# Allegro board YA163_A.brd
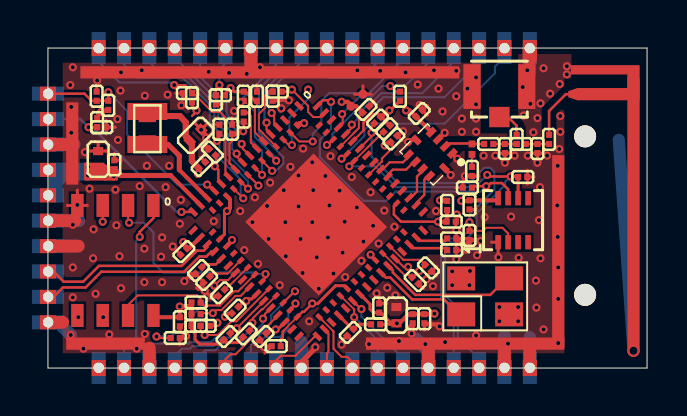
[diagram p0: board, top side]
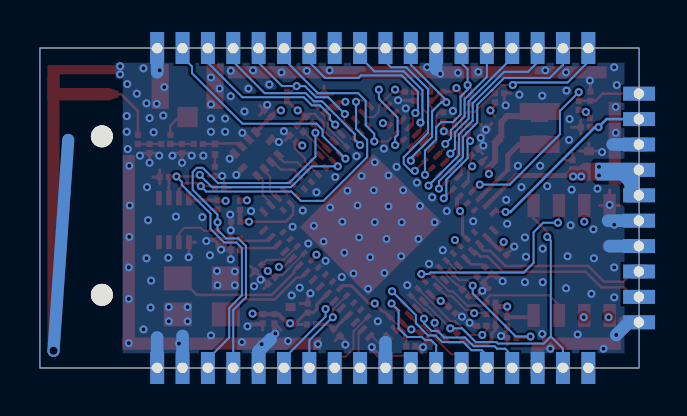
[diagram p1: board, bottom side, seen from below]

Outline 30 x 16 mm; copper layers: TOP, GND, PWR, BOTTOM. Coordinates in mm from the lower left corner of the outline.
Outline path: 0,16 0,13.96 arc(0.25,13.71) 0,13.47 0,12.69 arc(0.25,12.44) 0,12.2 0,11.42 arc(0.25,11.17) 0,10.93 0,10.15 arc(0.25,9.9) 0,9.66 0,8.88 arc(0.25,8.63) 0,8.39 0,7.61 arc(0.25,7.36) 0,7.12 0,6.34 arc(0.25,6.09) 0,5.85 0,5.07 arc(0.25,4.82) 0,4.58 0,3.8 arc(0.25,3.55) 0,3.31 0,2.53 arc(0.25,2.28) 0,2.04 0,0 2.29,0 arc(2.54,0.25) 2.79,0 3.56,0 arc(3.81,0.25) 4.06,0 4.83,0 arc(5.08,0.25) 5.33,0 6.1,0 arc(6.35,0.25) 6.6,0 7.37,0 arc(7.62,0.25) 7.87,0 8.64,0 arc(8.89,0.25) 9.14,0 9.91,0 arc(10.16,0.25) 10.41,0 11.18,0 arc(11.43,0.25) 11.68,0 12.45,0 arc(12.7,0.25) 12.95,0 13.72,0 arc(13.97,0.25) 14.22,0 14.99,0 arc(15.24,0.25) 15.49,0 16.26,0 arc(16.51,0.25) 16.76,0 17.53,0 arc(17.78,0.25) 18.03,0 18.8,0 arc(19.05,0.25) 19.3,0 20.07,0 arc(20.32,0.25) 20.57,0 21.34,0 arc(21.59,0.25) 21.84,0 22.61,0 arc(22.86,0.25) 23.11,0 23.88,0 arc(24.13,0.25) 24.38,0 30,0 30,16 24.38,16 arc(24.13,15.75) 23.88,16 23.11,16 arc(22.86,15.75) 22.61,16 21.84,16 arc(21.59,15.75) 21.34,16 20.57,16 arc(20.32,15.75) 20.07,16 19.3,16 arc(19.05,15.75) 18.8,16 18.03,16 arc(17.78,15.75) 17.53,16 16.76,16 arc(16.51,15.75) 16.26,16 15.49,16 arc(15.24,15.75) 14.99,16 14.22,16 arc(13.97,15.75) 13.72,16 12.95,16 arc(12.7,15.75) 12.45,16 11.68,16 arc(11.43,15.75) 11.18,16 10.41,16 arc(10.16,15.75) 9.91,16 9.14,16 arc(8.89,15.75) 8.64,16 7.87,16 arc(7.62,15.75) 7.37,16 6.6,16 arc(6.35,15.75) 6.1,16 5.33,16 arc(5.08,15.75) 4.83,16 4.06,16 arc(3.81,15.75) 3.56,16 2.79,16 arc(2.54,15.75) 2.29,16 0,16

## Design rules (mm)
net group DP_USB: nets USB_DNEG USB_DPOS
net group RFIN2NP1: nets RFIN2N1 RFIN2P1
net group RFIN2NPA2: nets RFIN2N1_ANT2 RFIN2P1_ANT2
net group RFOUT2NP1: nets RFOUT2N1 RFOUT2P1
net group RF50OHM: nets N34454485 N34454501 N34484478 N34484530 N34527590 N344546310
nets with their own width: min track width 0.152; nets GND

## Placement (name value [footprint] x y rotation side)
C2  0.1UF  [CAP-0201]  20.19 7.32 180 top
C4  0.1UF  [CAP-0201]  17.32 11.46 45 top
C6  0.1UF  [CAP-0201]  15.93 12.93 45 top
C7  2.2UF  [CAP-0402#2]  15.77 13.69 225 top
C8  0.1UF  [CAP-0201]  9.22 11.94 270 top
C9  0.1UF  [CAP-0201]  19.05 5 135 top
C10  0.1UF  [CAP-0201]  18.39 4.37 135 top
C12  0.1UF  [CAP-0201]  18.85 2.46 90 top
C13  0.1UF  [CAP-0201]  18.26 2.46 90 top
C14  0.1UF  [CAP-0201]  8.23 10.79 315 top
C16  0.1UF  [CAP-0201]  15.14 1.78 225 top
C17  0.1UF  [CAP-0201]  16.59 3 90 top
C19  470PF  [CAP-0201]  8.59 11.94 270 top
C20  0.1UF  [CAP-0201]  7.72 10.13 45 top
C22  4.7UF  [CAP-0402]  7.39 11.63 225 top
C23  4.7UF  [CAP-0402]  2.51 10.44 270 top
C25  0.1UF  [CAP-0201]  3.33 10.16 270 top
C26  0.1UF  [CAP-0201]  7.54 4.88 45 top
C28  0.1UF  [CAP-0201]  9.37 2.9 45 top
C29  0.1UF  [CAP-0201]  10.77 1.57 45 top
C30  0.1UF  [CAP-0201]  6.81 5.82 225 top
C32  0.1UF  [CAP-0201]  11.43 1.09 180 top
C58  4.3nH  [CAP-0201]  24.51 10.97 270 top
C59  0ohm  [CAP-0201]  25.1 11.43 270 top
C78  0.1UF  [CAP-0201]  2.44 13.59 270 top
C330  0.1UF  [CAP-0201]  6.6 2.31 90 top
C336  2.7pF  [CAP-0201]  23.7 11.2 180 top
C337  DNP  [CAP-0201]  23.47 11.43 270 top
C338  8.2pF  [CAP-0201]  22.07 11.2 180 top
C339  3.0nH  [CAP-0201]  22.89 10.97 270 top
C346  0.1UF  [CAP-0201]  21.11 8.15 270 top
C411  1.0UF  [CAP-0201]  18.59 12.73 225 top
C443  0.1UF  [CAP-0201]  10.46 13.59 270 top
C447  2.2UF  [CAP-0402]  17.45 2.64 270 top
C452  1.0nH  [CAP-0201]  21.23 9.83 270 top
C453  10PF  [CAP-0201]  20.22 6.48 0 top
C454  10PF  [CAP-0201]  20.22 5.89 0 top
C456  10PF  [CAP-0201]  21.11 6.63 270 top
C461  10PF  [CAP-0201]  23.77 9.55 0 top
H1  1D07  [STAMP0_7XT0_8B1_6D0_5]  24.13 16 0 top
H2  1D07  [STAMP0_7XT0_8B1_6D0_5]  22.86 16 0 top
H3  1D07  [STAMP0_7XT0_8B1_6D0_5]  21.59 16 0 top
H4  1D07  [STAMP0_7XT0_8B1_6D0_5]  20.32 16 0 top
H5  1D07  [STAMP0_7XT0_8B1_6D0_5]  19.05 16 0 top
H6  1D07  [STAMP0_7XT0_8B1_6D0_5]  17.78 16 0 top
H7  1D07  [STAMP0_7XT0_8B1_6D0_5]  16.51 16 0 top
H8  1D07  [STAMP0_7XT0_8B1_6D0_5]  15.24 16 0 top
H9  1D07  [STAMP0_7XT0_8B1_6D0_5]  13.97 16 0 top
H10  1D07  [STAMP0_7XT0_8B1_6D0_5]  12.7 16 0 top
H11  1D07  [STAMP0_7XT0_8B1_6D0_5]  11.43 16 0 top
H12  1D07  [STAMP0_7XT0_8B1_6D0_5]  10.16 16 0 top
H13  1D07  [STAMP0_7XT0_8B1_6D0_5]  8.89 16 0 top
H14  1D07  [STAMP0_7XT0_8B1_6D0_5]  7.62 16 0 top
H15  1D07  [STAMP0_7XT0_8B1_6D0_5]  6.35 16 0 top
H16  1D07  [STAMP0_7XT0_8B1_6D0_5]  5.08 16 0 top
H17  1D07  [STAMP0_7XT0_8B1_6D0_5]  3.81 16 0 top
H18  1D07  [STAMP0_7XT0_8B1_6D0_5]  2.54 16 0 top
H19  1D07  [STAMP0_7XT0_8B1_6D0_5]  0 13.71 270 top
H20  1D07  [STAMP0_7XT0_8B1_6D0_5]  0 12.44 270 top
H21  1D07  [STAMP0_7XT0_8B1_6D0_5]  0 11.17 270 top
H22  1D07  [STAMP0_7XT0_8B1_6D0_5]  0 9.9 270 top
H23  1D07  [STAMP0_7XT0_8B1_6D0_5]  0 8.63 270 top
H24  1D07  [STAMP0_7XT0_8B1_6D0_5]  0 7.36 270 top
H25  1D07  [STAMP0_7XT0_8B1_6D0_5]  0 6.09 270 top
H26  1D07  [STAMP0_7XT0_8B1_6D0_5]  0 4.82 270 top
H27  1D07  [STAMP0_7XT0_8B1_6D0_5]  0 3.55 270 top
H28  1D07  [STAMP0_7XT0_8B1_6D0_5]  0 2.28 270 top
H29  1D07  [STAMP0_7XT0_8B1_6D0_5]  2.54 0 0 top
H30  1D07  [STAMP0_7XT0_8B1_6D0_5]  3.81 0 0 top
H31  1D07  [STAMP0_7XT0_8B1_6D0_5]  5.08 0 0 top
H32  1D07  [STAMP0_7XT0_8B1_6D0_5]  6.35 0 0 top
H33  1D07  [STAMP0_7XT0_8B1_6D0_5]  7.62 0 0 top
H34  1D07  [STAMP0_7XT0_8B1_6D0_5]  8.89 0 0 top
H35  1D07  [STAMP0_7XT0_8B1_6D0_5]  10.16 0 0 top
H36  1D07  [STAMP0_7XT0_8B1_6D0_5]  11.43 0 0 top
H37  1D07  [STAMP0_7XT0_8B1_6D0_5]  12.7 0 0 top
H38  1D07  [STAMP0_7XT0_8B1_6D0_5]  13.97 0 0 top
H39  1D07  [STAMP0_7XT0_8B1_6D0_5]  15.24 0 0 top
H40  1D07  [STAMP0_7XT0_8B1_6D0_5]  16.51 0 0 top
H41  1D07  [STAMP0_7XT0_8B1_6D0_5]  17.78 0 0 top
H42  1D07  [STAMP0_7XT0_8B1_6D0_5]  19.05 0 0 top
H43  1D07  [STAMP0_7XT0_8B1_6D0_5]  20.32 0 0 top
H44  1D07  [STAMP0_7XT0_8B1_6D0_5]  21.59 0 0 top
H45  1D07  [STAMP0_7XT0_8B1_6D0_5]  22.86 0 0 top
H46  1D07  [STAMP0_7XT0_8B1_6D0_5]  24.13 0 0 top
J1  CON RF 3PIN  [CON-HRS-UFL]  22.61 12.55 0 top
L1  0  [IND-0201]  19.99 8.13 90 top
L4  4.7UH  [2PSM102X83N]  4.98 12.83 270 top
L427  1.0pF  [IND-0201#2]  21.23 11.2 270 top
NOREF  -  [unnamed]  26.9 11.58 0 top
NOREF#2  -  [unnamed]  26.9 3.66 0 top
R2  No Load  [RES-0201]  7.95 4.42 225 top
R5  No Load  [RES-0201]  8.69 3.76 225 top
R6  10K  [RES-0201]  7.42 2.11 0 top
R7  No Load  [RES-0201]  7.87 2.11 0 top
R8  No Load  [RES-0201]  11.48 13.82 180 top
R9  10K  [RES-0201]  11.25 13.59 270 top
R10  10K  [RES-0201]  3.02 13.13 90 top
R11  10K  [RES-0201]  8.41 13.41 270 top
R12  No Load  [RES-0201]  8.64 13.64 180 top
R13  10K  [RES-0201]  6.99 13.74 180 top
R14  No Load  [RES-0201]  7.21 13.51 90 top
R16  10K  [RES-0201]  9.8 12.55 90 top
R17  10K  [RES-0201]  17.63 13.59 90 top
R18  NL  [RES-0201]  9.8 13.59 270 top
R20  No Load  [RES-0201]  6.38 1.5 0 top
R21  No Load  [RES-0201]  2.69 12.04 0 top
R22  10K  [RES-0201]  2.46 12.27 270 top
R24  0  [RES-0201]  16.41 2.18 180 top
R305  10K  [RES-0201]  7.42 2.69 180 top
R306  10K  [RES-0201]  9.93 1.7 225 top
R307  10K  [RES-0201]  7.42 3.28 180 top
R308  10K  [RES-0201]  8.97 1.57 225 top
R309  2K2  [RES-0201]  16.51 12.4 45 top
R310  2K2  [RES-0201]  16.97 11.96 45 top
R330  No Load  [RES-0603]  4.98 11.96 270 top
R331  10K  [2P0201R_RF]  21.01 9.02 0 top
U1  ASIC_QCA4010_117P_117PIN  [117PSM358X358N197]  12.57 13.11 225 top
U3  W25Q16DVSNIG  [8PSO202X163G50]  5.28 8.13 180 top
U22  MFI337S3959_8P  [QFN8_0P5_2P5X2P5]  23.29 7.39 90 top
U23  Balun_QCA4010  [BALUN-10P_2016]  19.15 10.69 45 top
Y1  40.000000MHZ  [CRY-SMD4-CX101F]  21.89 3.58 0 top

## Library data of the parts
C2 C4 C6 C8-C10 C12-C14 C16 C17 C19 C20 C25 C26 C28-C30 C32 C58 C78 C337 C346 C411 C443 C452 = CAP_HCAP_0: alternate symbols: (2P0201R_RF)
C7 C22 C23 C447 = CAP_HCAP_0: alternate symbols: (2P0402ROFS,2P0402R_RF,2P0402ROFS_RF)
C59 C330 C336 C338 C339 C453 C454 C456 C461 = CAP_HCAP_2PIN: alternate symbols: (2P0201R_RF)
H1-H46 = TP_0
J1 = CON RF 3PIN
L1 R2 R5-R9 R11-R14 R16-R18 R20-R22 R24 R305-R310 R331 = RESISTOR_HRES_2PIN: alternate symbols: (2P0201R_RF)
L4 = IND_MAG_HIND_MAG2PIN: User Part Number: 110-73520-0472
L427 = IND_POL_V1_HIND_POL_V1_2PIN: alternate symbols: (2P0201R_POLV1_RF)
R10 = RESISTOR_HRES_0: alternate symbols: (2P0201R_RF)
R330 = RES
U1 = ASIC_QCA4010_117P_117PIN: User Part Number: CD90-Y8681-1
U3 = W25X20BL_2: User Part Number: 272-74277-XXXX
U22 = MFI337S3959_8P
U23 = Balun_QCA4010
Y1 = CRYSTAL_4PIN_2G_V1_4PIN

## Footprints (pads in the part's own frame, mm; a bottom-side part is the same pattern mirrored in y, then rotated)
2P0201R_RF
  rect 0.305x0.305 smd: 1(-0.229,0) 2(0.229,0)
2PSM102X83N
  rect 0.851x1.999 smd: 1(0,0) 2(1.651,0)
8PSO202X163G50
  rect 0.62x1.15 smd: 1(0,0) 2(1.27,0) 3(2.54,0) 4(3.81,0) 5(3.81,5.5) 6(2.54,5.5) 7(1.27,5.5) 8(0,5.5)
117PSM358X358N197
  rect 0.22x0.5 smd: A1(0,0) A2(0.5,0) A3(1,0) A4(1.5,0) A5(2,0) A6(2.5,0) A7(3,0) A8(3.5,0) A9(4,0) A10(4.5,0) A11(5,0) A12(5.5,0) A13(6,0) A14(6.5,0) A15(7,0) A16(7.5,0) A33(7.5,8.8) A34(7,8.8) A35(6.5,8.8) A36(6,8.8) A37(5.5,8.8) A38(5,8.8) A39(4.5,8.8) A40(4,8.8) A41(3.5,8.8) A42(3,8.8) A43(2.5,8.8) A44(2,8.8) A45(1.5,8.8) A46(1,8.8) A47(0.5,8.8) A48(0,8.8)
  rect 0.5x0.22 smd: A17(8.15,0.65) A18(8.15,1.15) A19(8.15,1.65) A20(8.15,2.15) A21(8.15,2.65) A22(8.15,3.15) A23(8.15,3.65) A24(8.15,4.15) A25(8.15,4.65) A26(8.15,5.15) A27(8.15,5.65) A28(8.15,6.15) A29(8.15,6.65) A30(8.15,7.15) A31(8.15,7.65) A32(8.15,8.15) A49(-0.65,8.15) A50(-0.65,7.65) A51(-0.65,7.15) A52(-0.65,6.65) A53(-0.65,6.15) A54(-0.65,5.65) A55(-0.65,5.15) A56(-0.65,4.65) A57(-0.65,4.15) A58(-0.65,3.65) A59(-0.65,3.15) A60(-0.65,2.65) A61(-0.65,2.15) A62(-0.65,1.65) A63(-0.65,1.15) A64(-0.65,0.65)
  rect 0.22x0.35 smd: B1(0.75,0.625) B2(1.25,0.625) B3(1.75,0.625) B4(2.25,0.625) B5(2.75,0.625) B6(3.25,0.625) B7(3.75,0.625) B8(4.25,0.625) B9(4.75,0.625) B10(5.25,0.625) B11(5.75,0.625) B12(6.25,0.625) B13(6.75,0.625) B27(6.75,8.175) B28(6.25,8.175) B29(5.75,8.175) B30(5.25,8.175) B31(4.75,8.175) B32(4.25,8.175) B33(3.75,8.175) B34(3.25,8.175) B35(2.75,8.175) B36(2.25,8.175) B37(1.75,8.175) B38(1.25,8.175) B39(0.75,8.175)
  rect 0.35x0.22 smd: B14(7.525,1.4) B15(7.525,1.9) B16(7.525,2.4) B17(7.525,2.9) B18(7.525,3.4) B19(7.525,3.9) B20(7.525,4.4) B21(7.525,4.9) B22(7.525,5.4) B23(7.525,5.9) B24(7.525,6.4) B25(7.525,6.9) B26(7.525,7.4) B40(-0.025,7.4) B41(-0.025,6.9) B42(-0.025,6.4) B43(-0.025,5.9) B44(-0.025,5.4) B45(-0.025,4.9) B46(-0.025,4.4) B47(-0.025,3.9) B48(-0.025,3.4) B49(-0.025,2.9) B50(-0.025,2.4) B51(-0.025,1.9) B52(-0.025,1.4)
  rect 4.84x5.2 smd: EP117(3.585,4.798)
BALUN-10P_2016
  rect 0.5x0.3 smd: 1(0.8,-0.75) 2(0.8,-0.25) 3(0.8,0.25) 4(0.8,0.75) 6(-0.8,0.75) 7(-0.8,0.25) 8(-0.8,-0.25) 9(-0.8,-0.75)
  rect 0.3x0.5 smd: 5(0,1) 10(0,-1)
CAP-0201
  rect 0.305x0.305 smd: 1(-0.229,0) 2(0.229,0)
CAP-0402
  rect 0.406x0.508 smd: 1(-0.406,0) 2(0.406,0)
CAP-0402#2
  round 0.45 smd: 1(0,0) 2(0.85,0)
CON-HRS-UFL
  rect 1.016x1.016 smd: 1(0,0)
  rect 0.864x2.235 smd: 2(-1.372,1.524) 3(1.372,1.524)
CRY-SMD4-CX101F
  rect 1.4x1.2 smd: 1(-1.2,-0.9) 2(1.2,-0.9) 3(1.2,0.9) 4(-1.2,0.9)
IND-0201
  rect 0.305x0.305 smd: 1(-0.229,0) 2(0.229,0)
IND-0201#2
  rect 0.34x0.34 smd: 1(0,0) 2(0.52,0)
QFN8_0P5_2P5X2P5
  rect 0.711x0.279 smd: 1(-1.1,0.75) 2(-1.1,0.25) 3(-1.1,-0.25) 4(-1.1,-0.75) 5(1.1,-0.75) 6(1.1,-0.25) 7(1.1,0.25) 8(1.1,0.75)
RES-0201
  rect 0.305x0.305 smd: 1(-0.229,0) 2(0.229,0)
RES-0603
  rect 0.61x0.864 smd: 1(-0.635,0) 2(0.635,0)
STAMP0_7XT0_8B1_6D0_5
  rect 0.7x0.8 hole 0.5: 1(0,0)
unnamed
  round 1.1 hole 1.1 unplated: (0,0)

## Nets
DVDD12: C6.1(POS) C7.2(NEG) C20.1(POS) C22.2(NEG) C32.1(POS) L1.2(NEG) L4.1(POS) R330.1(PIN1) U1.B1(DVDD12#B1) U1.B11(DVDD12#B11) U1.B15(DVDD12#B15) U1.B26(DVDD12#B26) U1.B31(DVDD12#B31) U1.B49(DVDD12#B49)
GND: C2.1(POS) C4.2(NEG) C6.2(NEG) C7.1(POS) C8.1(POS) C9.1(POS) C10.1(POS) C12.1(POS) C13.1(POS) C14.1(POS) C16.2(NEG) C17.2(NEG) C19.1(POS) C20.2(NEG) C22.1(POS) C23.1(POS) C25.1(POS) C26.1(POS) C28.1(POS) C29.1(POS) C30.2(NEG) C32.2(NEG) C58.2(NEG) C78.1(POS) C330.1(POS) C339.2(NEG) C346.2(NEG) C411.1(POS) C443.1(POS) C447.1(POS) C452.2(NEG) C453.2(NEG) C454.2(NEG) C456.2(NEG) C461.2(NEG) H1.1 H12.1 H21.1 H24.1 H25.1 H28.1 H31.1 H37.1 H42.1 H45.1 H46.1 J1.2 J1.3 R2.2(NEG) R5.2(NEG) R7.2(NEG) R9.2(NEG) R11.2(NEG) R13.2(NEG) R20.2(NEG) R21.2(NEG) R331.1(POS) U1.EP117(GND_PAD) U3.4(GND) U22.1(GND) U23.1(GND0) U23.3(GND1) U23.5(GND2) U23.10(GND3) Y1.2(GND1) Y1.4(GND2)
VDD12_RF: C2.2(NEG) C9.2(NEG) C10.2(NEG) L1.1(POS) U1.B36(VDD12_BB_PLL) U1.B37(VDD12_SYNTH) U1.B41(VDD12_RF1)
VDD33: C4.1(POS) C8.2(NEG) C12.2(NEG) C13.2(NEG) C14.2(NEG) C17.1(POS) C23.2(NEG) C25.2(NEG) C28.2(NEG) C29.2(NEG) C30.1(POS) C330.2(NEG) C346.1(POS) C411.2(NEG) C443.2(NEG) C447.2(NEG) H22.1 H23.1 R6.1(POS) R8.1(POS) R10.1(POS) R12.1(POS) R14.1(POS) R16.1(POS) R17.1(POS) R18.1(POS) R22.1(POS) R24.1(POS) R305.2(NEG) R306.2(NEG) R307.2(NEG) R308.2(NEG) R309.2(NEG) R310.2(NEG) U1.A6(VDDIO_SDIO_1) U1.A10(VDDIO_SDIO_0) U1.A12(VDDIO_SDIO_PMU) U1.A15(SWREG_IN) U1.A18(VDD33_PMUUSB) U1.A26(VDDIO_GPIO_3) U1.A30(VDDIO_GPIO_2) U1.A39(VDD33_ANT) U1.A44(VDD33_SYNTH) U1.A59(VDDIO_GPIO_1) U1.A63(VDDIO_GPIO_0) U1.B16(VDD33_IOT) U1.B35(VDD33_PLL_XTAL) U1.B45(VDD33_RF1) U3.8(VCC) U22.8(VCC) U23.4(DC)
VDD33_ADC: C16.1(POS) R24.2(NEG) U1.A36(VDD33_ADC)
VDD_1P8: C26.2(NEG) U1.A21(VDD_1P8_OUT)
ADC0: H41.1 U1.A38(ADC_0)
ADC1: H40.1 U1.B30(ADC_1)
ADC6_UART_R: H38.1 U1.A34(ADC_6)
ADC7_UART_T: H39.1 U1.B27(ADC_7)
CHIP_PWD_L: C78.2(NEG) H19.1 R10.2(NEG) U1.A13(C\H\I\P\_\P\W\D\)
GPIO7: R16.2(NEG) U1.A7(GPIO7)
GPIO9: R8.2(NEG) R9.1(POS) U1.B4(GPIO9)
GPIO_IOE0: R5.1(POS) U1.B19(GPIO_IOE[0])
GPIO_IOE1: H29.1 R20.1(POS) U1.A23(GPIO_IOE[1])
GPIO_IOE2: R2.1(POS) U1.B18(GPIO_IOE[2])
I2CM_SCK0: C461.1(POS) H44.1 R310.1(POS) U1.B47(GPIO26) U22.6(SCL)
I2CM_SDA0: C456.1(POS) H43.1 R309.1(POS) U1.A58(GPIO25) U22.2(SDA)
IOT_MODE_EN: H20.1 R21.1(POS) R22.2(NEG) U1.A16(IOT_MODE_EN)
MFI_RST: R331.2(NEG) U1.A64(GPIO16) U22.7(RST)
PWM0: H10.1 U1.B6(GPIO6)
PWM2: H11.1 R18.2(NEG) U1.B5(GPIO8)
PWM4_I2CS_SCK0: H9.1 U1.A5(GPIO10)
PWM5_I2CS_SDA0: H8.1 U1.B3(GPIO11)
PWM6: H7.1 U1.A4(GPIO12)
PWM7: H6.1 U1.B2(GPIO13)
RFIN2N1: U1.A51(RFIN2N1) U23.8(RX_N)
RFIN2N1_ANT2: C454.1(POS) U1.A46(RFIN2N1_ANT2)
RFIN2P1: U1.A50(RFIN2P1) U23.9(RX_P)
RFIN2P1_ANT2: C453.1(POS) U1.A47(RFIN2P1_ANT2)
RFOUT2N1: U1.A55(RFOUT2N1) U23.6(TX_N)
RFOUT2P1: U1.A54(RFOUT2P1) U23.7(TX_P)
SDIO_D2_UART2_TXD: H16.1 U1.B8(GPIO2)
SPI_CLK_SDIO_CLK_UART2_CTS: H14.1 U1.A8(GPIO5)
SPI_CS_SDIO_CMD: H18.1 R13.1(POS) R14.2(NEG) U1.A11(GPIO0)
SPI_INT_SDIO_D1_UART2_RXD: H15.1 U1.A9(GPIO3)
SPI_MISO_SDIO_D0_UART2_RTS: H13.1 R11.1(POS) R12.2(NEG) U1.B7(GPIO4)
SPI_MOSI_SDIO_D3: H17.1 U1.B9(GPIO1)
SPIM_CLK: R306.1(POS) U1.B23(GPIO34) U3.6(CLK)
SPIM_CS: H30.1 R308.1(POS) U1.A27(GPIO35) U3.1(\\C\S\)
SPIM_DIO2: R305.1(POS) U1.A25(GPIO38) U3.3(\\W\P\)
SPIM_DIO3: R307.1(POS) U1.B20(GPIO39) U3.7(\\H\O\L\D)
SPIM_MISO_DIO1: U1.B21(GPIO37) U3.2(DO)
SPIM_MOSI_DIO0: R6.2(NEG) R7.1(POS) U1.B22(GPIO36) U3.5(DI)
USB_DNEG: H27.1 U1.A20(USB_DNEG)
USB_DPOS: H26.1 U1.A19(USB_DPOS)
WIFI_HSUART_CTS: H4.1 U1.B50(GPIO22)
WIFI_HSUART_RTS: H5.1 R17.2(NEG) U1.A61(GPIO21)
WIFI_HSUART_RXD: H3.1 U1.A60(GPIO23)
WIFI_HSUART_TXD: H2.1 U1.B48(GPIO24)
WIFI_I2S_BLK1: H36.1 U1.A33(GPIO27)
WIFI_I2S_MCLK1: H32.1 U1.A28(GPIO33)
WIFI_I2S_SDI1: H35.1 U1.B25(GPIO30)
WIFI_I2S_SDO1: H34.1 U1.A29(GPIO31)
WIFI_I2S_WS1: H33.1 U1.B24(GPIO32)
N34434236: U1.A43(XTALI) Y1.3(N2)
N34434434: C19.2(NEG) U1.B10(SREG_OUT)
N34434436: L4.2(NEG) R330.2(PIN2) U1.A14(SWREG_OUT)
N34439993: U1.A37(ADC_2)
N34440006: U1.B29(ADC_3)
N34450965: U1.A42(XTALO) Y1.1(N1)
N34454485: C58.1(POS) C59.2(NEG) C336.1(POS)
N34454501: C59.1(POS)
N34484478: C337.1(POS) J1.1
N34484530: C336.2(NEG) C337.2(NEG) C338.1(POS) C339.1(POS)
N34527590: C338.2(NEG) L427.1(POS) U23.2(ANT)
N344546310: C452.1(POS) L427.2(NEG)

Pads without a net: U1 A1 A2 A3 A17 A22 A24 A31 A32 A35 A40 A41 A45 A48 A49 A52 A53 A56 A57 A62 B12 B13 B14 B17 B28 B32 B33 B34 B38 B39 B40 B42 B43 B44 B46 B51 B52; U22 3 4 5

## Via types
v1: diameter 0.406, hole 0.203, TOP to BOTTOM, 274 vias
v2: diameter 0.61, hole 0.406, TOP to BOTTOM, 1 via

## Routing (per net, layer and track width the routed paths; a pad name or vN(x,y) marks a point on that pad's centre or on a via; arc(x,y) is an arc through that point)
DVDD12: length 42.2
  TOP w0.089: U1.B26 11.81,1.88 ; 15.29,11.72 U1.B49
  TOP w0.102: 11.81,1.88 11.76,1.83 ; 15.29,11.72 15.57,12 15.57,12.57 15.76,12.77 ; R330.1 L4.1
  TOP w0.127: 11.76,1.83 11.76,1.52 11.66,1.42 C32.1 ; U1.B26 12.74,2.81 12.83,2.81 13.23,3.22
  TOP w0.152: v1(13.23,3.23) 13.23,3.22 13.51,3.22 14.4,4.11 14.85,4.11 14.99,3.97 ; v1(8.97,7.85) 8.84,7.72 8.84,6.69 U1.B15
  TOP w0.203: v1(12.83,12.24) 12.59,12.24 U1.B1 ; v1(8.97,7.85) 9.12,8 9.12,8.43 U1.B11 ; 15.76,12.77 15.44,13.09 C7.2 15.17,13.15 15.01,13.31 v1(14.71,13.31)
  TOP w0.254: v1(19.63,8.38) 19.96,8.38 L1.2
  TOP w0.305: R330.1 6.61,12.6 6.9,12.28 6.9,11.58 7,11.47 C22.2 7.21,11.24 7.21,10.35 7.56,9.97 7.56,9.74 v1(7.52,9.7)
  PWR w0.203: 14.2,12.24 14.2,12.75 14.71,13.26 v1(14.71,13.31) ; 14.2,12.24 v1(12.83,12.24) ; 14.2,12.24 14.2,11.99 17.81,8.38 v1(19.63,8.38) ; v1(13.23,3.23) 12.8,3.66 12.8,4.01 v1(8.97,7.85)
  PWR w0.305: v1(7.52,9.7) 7.52,8.81 8.48,7.85 v1(8.97,7.85) 8.97,9.09 12.12,12.24 v1(12.83,12.24)
GND: length 120.6
  TOP w0.152: C346.2 21.45,7.92 ; C7.1 15.77,14.11 ; C7.1 15.36,13.69 ; C7.1 16.19,13.69 ; C9.1 19.45,5.09 ; C9.1 19.45,4.6 ; C9.1 18.97,4.6 ; 6.41,13.74 R13.2 6.76,13.4 ; 7.36,12.24 C22.1 ; C22.1 v1(7.67,11.91) ; C22.1 7.96,12.2 ; C22.1 7.99,11.61 ; 10.37,1.17 C29.1 10.61,1.38 10.9,1.09 C32.2 10.86,0.75 ; 7.14,4.47 C26.1 ; C26.1 7.18,4.72 6.99,4.52 ; C26.1 7.79,4.31 R2.2 7.55,4.02 ; 18.85,1.89 C12.1 19.19,2.24 ; 20.43,9.02 R331.1 20.78,9.36 ; v1(20.88,9.6) C452.2 21.58,9.6 ; 22.54,5.74 U22.1 22.21,6.29 ; 19.85,11.75 U23.3 19.54,11.44 v1(19.86,11.76) ; 2.92,12.04 3.38,12.04 ; 2.92,12.04 2.92,12.38 ; 2.92,12.04 2.92,11.7 ; v1(20.5,10.46) 20.25,10.71 U23.1 20.49,10.49 ; U3.4 v1(1.47,8.15) 1.47,8.89 ; U3.4 0.97,8.13 ; U3.4 1.97,8.13 ; U3.4 1.47,7.36 ; C330.1 6.6,1.88 6.91,1.57 ; 16.97,3.23 C17.2 16.59,3.57 ; C461.2 24.35,9.55 ; C461.2 24,9.21 ; C461.2 24,9.89 ; C8.1 9.22,12.51 ; C6.2 16.33,13.33 ; 18.51,13.13 18.75,12.89 ; 18.75,12.89 19,12.64 ; 18.75,12.89 19,13.13 ; v1(20.17,9.65) 19.86,9.96 U23.10 20.17,9.67 ; 14.73,1.37 C16.2 15.22,1.37 ; 20.45,5.55 C454.2 ; C454.2 C453.2 ; C454.2 20.79,5.89 ; 6.4,5.9 6.65,5.66 ; 8.24,12.17 C19.1 ; 17.73,11.86 17.48,11.62 17.73,11.37 ; C453.2 20.74,6.18 20.74,6.08 20.76,6.06 C456.2 21.03,6.48 C453.2 ; C453.2 20.45,6.82 ; 3.33,10.73 C25.1 3.67,10.39 ; R11.2 8.75,13.18 ; C78.1 2.44,14.16 ; v1(12.06,13.39) 11.28,13.39 R9.2 11.6,13.36 ; 9.21,2.73 9.03,2.73 v1(8.86,2.57) ; 24.17,10.74 C58.2 ; C58.2 24.51,10.4 ; C58.2 24.85,10.74 ; 22.89,10.4 C339.2 ; C339.2 23.23,10.74 ; C339.2 22.54,10.74 ; 6.91,1.57 6.91,1.52 6.88,1.5 R20.2 6.6,1.16 ; 6.91,1.57 v1(6.91,1.6) ; 20.42,6.97 C2.1 ; 8.16,3.48 R5.2 8.16,3.6 8.14,3.57 v1(7.85,3.86) 7.77,3.94 7.52,3.94 7.44,4.01 ; 18.07,11.34 U23.5 18.13,11.4 v1(18.03,11.3) ; C443.1 10.46,14.16 ; 7.64,10.54 C20.2 ; 17.92,1.89 C13.1 ; C23.1 2.51,11.24 ; C23.1 2.07,10.85 ; C23.1 2.96,10.85 ; v1(8.48,2.26) 8.33,2.11 R7.2 ; 18.79,3.96 C10.1 18.79,4.45 ; 7.83,11.2 C14.1 7.83,10.71 ; v1(13.39,1.04) 13.39,0.99
  TOP w0.203: C12.1 18.9,2.18 19.51,2.18 v1(19.61,2.08) ; C13.1 18.26,1.78 v1(18.21,1.73) ; C456.2 21.62,6.4 ; C456.2 21.11,6.43 ; C456.2 21.11,5.99
  TOP w0.254: H37.1 12.7,0.3 13.39,0.99
  TOP w0.61: v2(29.32,0.86) 29.32,14.41
  TOP w0.635: H31.1 5.08,0.99 ; H45.1 22.86,0.97 ; H24.1 1.35,7.36 ; H28.1 0.74,2.28 ; H46.1 24.13,1.02 ; H21.1 1.24,11.17 ; H25.1 1.52,6.09 ; H42.1 19.05,0.91 ; H12.1 10.16,15.06
  TOP w0.711: H1.1 24.13,15.44
  GND w0.635: H12.1 10.16,14.81 ; H24.1 1.42,7.36 ; H46.1 24.13,1.35 ; H21.1 1.52,11.17 ; H42.1 19.05,1.27 ; H37.1 12.7,1.22 ; H45.1 22.86,1.27 ; H31.1 5.08,0.99 4.65,1.42 ; 1.52,1.63 0.86,2.28 H28.1 ; H1.1 24.13,15.04 ; H25.1 1.24,6.09
  PWR w0.635: H25.1 1.47,6.09 ; H46.1 24.13,1.32 ; H28.1 0.81,2.28 1.17,1.93 ; H21.1 1.65,11.17 ; H45.1 22.86,1.27 ; H42.1 19.05,1.35 ; H24.1 1.52,7.36 ; H1.1 24.13,14.68 ; H31.1 5.08,0.84 ; H37.1 12.7,1.17 ; H12.1 10.16,15.01
  BOTTOM w0.61: v2(29.32,0.86) 28.58,11.4
  BOTTOM w0.635: H12.1 10.16,14.94 ; H25.1 1.47,6.09 ; H45.1 22.86,1.6 ; 18.44,1.45 19.05,0.84 H42.1 ; H37.1 12.7,1.3 ; H21.1 1.32,11.17 ; H1.1 24.13,14.78 ; H24.1 1.55,7.36 ; H46.1 24.13,1.52 ; v1(1.14,1.65) 0.51,2.28 H28.1
  vias: v1(1.12,14.15) v1(1.24,15.04) v1(1.17,13.06) v1(1.17,11.76) v1(1.24,7.16) v1(1.24,5.03) v1(1.24,3.53) v1(1.78,0.97) v1(1.85,10.79) v1(2.08,8.97) v1(2.29,6.93) v1(2.26,5.49) v1(2.39,3.71) v1(2.46,14.38) v1(3.07,1.68) v1(3.38,8.92) v1(3.43,7.14) v1(3.48,12.45) v1(3.51,11.4) v1(3.63,13.87) v1(3.58,5.59) v1(3.66,14.78) v1(3.66,3.99) v1(4.45,0.97) v1(4.6,9.09) v1(4.7,14.88) v1(4.83,5.97) v1(4.83,4.29) v1(4.85,13.61) v1(4.85,1.7) v1(4.95,10.11) v1(5.71,6.53) v1(5.66,5.56) v1(5.71,4.29) v1(5.89,9.04) v1(5.99,13.67) v1(6.07,10.11) v1(6.25,6.07) v1(6.6,7.21) v1(6.68,13.13) v1(6.65,8.41) v1(6.83,4.34) v1(7.8,11.13) v1(7.92,11.51) v1(8.05,14.81) v1(8.31,7.34) v1(9.07,14.76) v1(9.32,12.85) v1(9.63,7.85) v1(9.83,5.89) v1(9.96,14.71) v1(10.24,7.29) v1(10.36,8.53) v1(10.52,5.21) v1(10.62,15.04) v1(10.82,1.04) v1(10.97,8.1) v1(11.05,6.45) v1(11.13,9.27) v1(11.61,4.14) v1(11.68,12.98) v1(11.81,8.89) v1(11.89,7.29) v1(11.91,5.59) v1(12.14,10.06) v1(12.55,9.63) v1(12.55,8.08) v1(12.65,6.45) v1(12.78,10.97) v1(12.75,4.75) v1(13.08,2.34) v1(13.23,10.29) v1(13.23,7.29) v1(13.28,8.89) v1(13.46,5.54) v1(13.56,3.96) v1(13.89,9.6) v1(14.02,6.53) v1(14.15,10.59) v1(14.1,8.13) v1(14.3,4.72) v1(14.61,8.86) v1(14.71,1.17) v1(14.76,5.77) v1(14.86,7.32) v1(14.88,4.55) v1(15.21,9.55) v1(15.49,14.88) v1(15.47,8.03) v1(15.7,5.36) v1(15.8,6.32) v1(16.08,1.19) v1(16.15,8.79) v1(16.28,7.11) v1(16.46,3.73) v1(16.64,14.86) v1(16.56,6.22) v1(16.84,7.87) v1(16.99,4.01) v1(17.35,7.06) v1(17.4,3.63) v1(17.58,1.35) v1(17.78,11.84) v1(17.91,14.78) v1(18.52,14.17) v1(18.62,13.16) v1(18.95,4.42) v1(18.9,1.19) v1(19.33,14.88) v1(19.28,4.09) v1(19.43,7.85) v1(19.56,13.97) v1(19.76,12.83) v1(19.89,1.3) v1(20.24,4.83) v1(20.24,4.14) v1(20.45,14.86) v1(20.45,13.59) v1(20.45,6.88) v1(20.45,5.44) v1(20.47,7.67) v1(20.73,12.47) v1(20.73,11.81) v1(20.93,5.92) v1(21.01,13.97) v1(21.13,4.85) v1(21.11,4.14) v1(21.44,14.53) v1(21.44,13.18) v1(21.44,12.47) v1(21.44,11.81) v1(21.44,1.63) v1(21.49,5.64) v1(21.67,6.35) v1(21.82,10.62) v1(21.87,7.54) v1(22.4,10.62) v1(22.56,5.54) v1(22.61,3.05) v1(22.61,2.34) v1(22.89,10.26) v1(23.04,1.22) v1(23.19,7.57) v1(23.37,10.62) v1(23.55,3.05) v1(23.55,2.34) v1(23.57,5.51) v1(23.77,14.05) v1(23.83,12.62) v1(24,14.88) v1(24.03,10.62) v1(24.16,13.21) v1(24.31,11.79) v1(24.43,4.37) v1(24.51,12.5) v1(24.51,10.26) v1(24.46,3.02) v1(24.64,9.04) v1(24.59,7.39) v1(24.66,13.23) v1(24.66,5.49) v1(24.82,14.99) v1(24.82,1.93) v1(24.99,10.62) v1(25.15,13.72) v1(25.53,10.11) v1(25.5,8.13) v1(25.53,6.55) v1(25.63,14.2) v1(25.6,10.95) v1(25.55,5.03) v1(25.55,3.45) v1(25.55,1.24) v1(25.65,12.6) v1(25.65,11.81) v1(25.98,15.09) v1(25.98,14.68)
VDD12_RF: length 11.9
  TOP w0.089: 17.79,5.42 17.13,6.07 17.13,6.07 U1.B37 ; 17.44,5.07 16.77,5.73 U1.B36
  TOP w0.102: 17.44,5.07 17.86,4.65 18.11,4.65 C10.2 ; C9.2 18.64,5.41 17.8,5.41 17.79,5.42
  TOP w0.127: v1(19.53,7.32) 17.68,7.32 17.32,7.67 17.32,8.1 U1.B41 ; C9.2 18.89,5.15 v1(18.59,4.85) 18.27,4.53 C10.2
  TOP w0.203: v1(19.53,7.32) C2.2 19.99,7.34 L1.1
  PWR w0.203: v1(19.53,7.32) 19.53,5.79 v1(18.59,4.85)
VDD33: length 114
  TOP w0.089: U1.B45 16.45,10.06 16.7,10.31 ; 16.41,5.38 16.15,5.64 v1(16.15,5.66)
  TOP w0.102: v1(12.22,13.92) 13.03,13.11 13.03,12.8 13.28,12.55 13.64,12.55 U1.A63 ; C443.2 10.46,13.11 10.36,13 10.36,11.79 10.81,11.34 U1.A6 ; 16.7,10.31 16.72,10.33 16.72,10.47 17.25,11 17.25,11.21 C4.1 ; U1.A44 17.39,5.47 17.81,5.05 v1(18.03,5.05) ; C23.2 2.49,10.06 v1(2.01,10.06) ; U1.A59 15.8,11.88 ; U1.A10 9.09,10.22 9.09,11.23 9.22,11.35 C8.2
  TOP w0.127: U1.A12 8.53,9.37 8.53,9.91 v1(8.36,10.08) 8.43,10.16 8.43,10.59 C14.2 ; 7.22,12.61 7.47,12.85 v1(7.44,12.88) 7.21,13.11 R14.1 ; R309.2 16.53,12.7 16.23,12.7 15.8,12.27 15.8,11.88
  TOP w0.152: C443.2 10.36,13.36 9.9,13.82 R18.1 9.32,13.82 v1(9.14,14) 8.86,13.72 R12.1 ; C29.2 11.05,1.85 11.33,1.85 v1(11.4,1.93) 11.51,1.93 U1.A30 ; U1.A26 10.2,3.45 10.03,3.45 v1(9.93,3.35) 9.88,3.3 9.78,3.3 C28.2 ; U1.A39 16.13,3.19 16.13,2.95 16.31,2.77 C17.1 16.66,2.77 17.2,2.24 C447.2 17.4,2.18 R24.1 ; R306.2 9.5,1.27 8.94,1.27 8.8,1.41 R308.2 8.59,1.19 7.59,1.19 7.37,1.42 7.37,1.73 7.19,1.91 R6.1 ; v1(9.78,11.84) 9.78,11.94 9.8,11.96 9.8,12.32 ; R22.1 2.46,12.6 v1(2.67,12.8) 2.77,12.9 R10.1 ; v1(12.22,13.92) 12.12,13.82 R8.1 ; R17.1 17.14,12.88 v1(17.09,12.88) ; v1(16.87,11.13) 17.03,11.29 C4.1 ; 16.7,12.56 17.13,12.12
  TOP w0.203: C8.2 9.53,11.71 9.65,11.84 v1(9.78,11.84) ; v1(6.6,3.07) C330.2 5.37,2.54 U3.8 ; v1(17.48,2.24) 17.6,2.24 18.06,2.69 C13.2 C12.2 19.33,2.69 v1(19.35,2.72) ; U1.A15 6.15,9.63 ; U1.B16 9.22,6.36 v1(9.22,6.4) ; R309.2 16.7,12.56 17.02,12.88 v1(17.09,12.88) ; v1(6.78,6.3) 6.78,6.17 C30.1 7.07,5.98 U1.A18 ; v1(20.7,8.36) 21.08,8.36 C346.1 22.43,8.38 U22.8 ; R305.2 R6.1 ; v1(17.93,12.88) 18.12,12.88 C411.2 19.21,11.78 19.19,11.78 U23.4
  TOP w0.254: 7.19,3.07 R307.2 ; 7.19,3.07 v1(6.6,3.07) ; 7.19,3.07 R305.2 ; C23.2 2.87,10.03 2.97,9.93 C25.2 3.63,9.63 6.15,9.63 ; v1(17.48,2.24) C447.2
  PWR w0.152: v1(18.03,5.05) 18.03,4.8 18.59,4.24 18.59,3.48 v1(19.35,2.72) ; v1(2.67,12.8) 2.9,12.57 v1(2.9,9.58) ; v1(17.48,2.24) 17.86,2.62 17.86,3.96 v1(16.15,5.66)
  PWR w0.203: 6.96,12.4 9.22,12.4 v1(9.78,11.84) ; 5.59,11.02 7.21,11.02 8.15,10.08 v1(8.36,10.08) ; v1(2.9,9.58) v1(3.3,9.58)
  PWR w0.254: v1(9.14,14) 9.25,14.1 12.04,14.1 v1(12.22,13.92) 12.65,13.49 13.26,13.49 13.84,14.07 15.27,14.07 16.43,12.9 17.04,12.9 17.09,12.85 ; 17.09,12.85 17.09,11.35 v1(16.87,11.13) 16.87,10.31 18.03,9.14 20.37,9.14 20.7,8.81 v1(20.7,8.36) ; 17.09,12.85 v1(17.09,12.88) 17.09,12.9 17.14,12.85 17.93,12.85 ; v1(6.6,3.07) 6.3,3.38 6.3,4.85 6.78,5.33 v1(6.78,6.3) ; 17.93,12.85 v1(17.93,12.88) ; 17.93,12.85 17.96,12.83 ; v1(11.4,1.93) 11.89,1.93 12.06,1.75 16.99,1.75 v1(17.48,2.24)
  PWR w0.305: v1(11.4,1.93) 11.56,2.08 11.56,3.02 11.23,3.35 v1(9.93,3.35) 9.22,4.06 v1(9.22,6.4) 6.88,6.4 v1(6.78,6.3) 6.71,6.3 3.51,9.5 3.51,9.58 ; 3.51,9.58 3.63,9.58 4.8,10.74 5.31,10.74 v1(7.44,12.88) 7.82,13.26 8.41,13.26 v1(9.14,14) ; 3.51,9.58 v1(3.3,9.58)
  vias: v1(2.01,9.63)
VDD33_ADC: length 2
  TOP w0.152: R24.2 15.54,2.18 C16.1 15.25,1.94 U1.A36
VDD_1P8: length 1.2
  TOP w0.127: C26.2 7.85,5.18 8.41,5.18 8.68,5.46 U1.A21
ADC0: length 4.4
  TOP w0.102: v1(15.7,2.95) 15.67,2.95 15.27,3.35 U1.A38
  BOTTOM w0.102: H41.1 17.78,0.48 15.7,2.56 v1(15.7,2.95)
ADC1: length 4.4
  TOP w0.089: U1.B30 14.65,3.61 15.32,2.94
  TOP w0.102: 15.32,2.94 15.33,2.93 v1(15.33,2.54)
  BOTTOM w0.102: H40.1 16.51,1.38 15.33,2.56 v1(15.33,2.54)
ADC6_UART_R: length 2
  TOP w0.102: U1.A34 13.85,1.93 14.05,1.73 14.05,0.81 13.97,0.74 H38.1
ADC7_UART_T: length 3.4
  TOP w0.089: 14.25,1.88 13.58,2.55 U1.B27
  TOP w0.102: 14.25,1.88 14.3,1.83 14.3,0.97 14.71,0.56 14.99,0.56 15.24,0.3 H39.1
CHIP_PWD_L: length 11.6
  TOP w0.102: v1(7.98,9.17) 8.03,9.17 8.33,8.87 U1.A13
  TOP w0.127: v1(3.02,13.79) R10.2 C78.2 2.18,13.36 1.83,13.71 H19.1
  BOTTOM w0.102: v1(7.98,9.17) 6.48,9.17 3.96,11.68 3.96,12.85 v1(3.02,13.79)
GPIO7: length 2.2
  TOP w0.102: 10.45,10.98 U1.A7 10.16,11.28 10.16,12.6 9.98,12.78 R16.2
GPIO9: length 3.5
  TOP w0.089: U1.B4 10.77,11.72
  TOP w0.102: 10.77,11.72 10.57,11.93 10.57,12.7 10.87,13 10.87,13.61 11.07,13.82 R8.2
GPIO_IOE0: length 1.6
  TOP w0.089: U1.B19 10.01,5.03 9.33,4.35
  TOP w0.102: R5.1 9.09,4.17 9.14,4.17 9.33,4.35
GPIO_IOE1: length 10.1
  TOP w0.102: R20.1 5.54,1.5 5.44,1.6 v1(5.44,1.57) ; U1.A23 9.39,4.76 9.02,4.39 8.61,4.39 v1(8.33,4.12)
  PWR w0.102: v1(5.44,1.57) 5.18,1.32 3.33,1.32 2.54,0.53 H29.1
  BOTTOM w0.102: v1(5.44,1.57) 6.17,1.57 8.33,3.73 v1(8.33,4.12)
GPIO_IOE2: length 1.9
  TOP w0.089: 8.96,4.72 9,4.72 9.43,5.16 9.43,5.16 9.65,5.38 U1.B18
  TOP w0.102: R2.1 8.25,4.72 8.96,4.72
I2CM_SCK0: length 24.7
  TOP w0.089: U1.B47 15.35,10.37 15.99,11.01
  TOP w0.102: v1(15.09,10.08) 15.09,10.11 15.34,10.37 U1.B47 ; R310.1 16.78,11.8 15.99,11.01
  TOP w0.127: v1(22,9.65) 22.07,9.58 v1(23.16,9.58) 23.52,9.58 C461.1
  TOP w0.152: C461.1 23.54,9.55 U22.6
  BOTTOM w0.102: v1(15.09,10.08) 16.38,10.08 17.42,9.04 21.39,9.04 v1(22,9.65) ; H44.1 21.59,0.45 20.52,1.52 20.52,3 19.89,3.63 19.89,5.99 20.17,6.27 20.78,6.27 21.46,6.96 21.46,7.72 22.9,9.15 22.9,9.31 v1(23.16,9.58)
I2CM_SDA0: length 24.4
  TOP w0.102: R309.1 16.21,12.09 v1(16.21,11.76) 16.21,11.58 15.61,10.99 15.61,10.98 ; U22.2 23.04,6.73 22.76,7.01 21.95,7.01 21.79,6.86 C456.1 v1(21.11,7.29)
  BOTTOM w0.102: H43.1 20.32,2.9 19.68,3.53 19.68,6.1 20.07,6.48 20.68,6.48 21.11,6.91 v1(21.11,7.29) 21.11,7.67 22.35,8.92 22.35,9.8 22.14,10.01 21.85,10.01 21.09,9.25 17.53,9.25 16.21,10.57 v1(16.21,11.76)
  BOTTOM w0.127: H43.1 20.32,-0.03
IOT_MODE_EN: length 9.6
  TOP w0.127: v1(2.03,12.04) R22.2 ; U1.A16 v1(6.69,7.8)
  BOTTOM w0.127: v1(6.69,7.8) 6.45,7.8 2.21,12.04 v1(2.03,12.04) 1.63,12.44 H20.1
MFI_RST: length 15.8
  TOP w0.102: 13.49,13.11 U1.A64
  TOP w0.127: 13.49,13.11 13.77,13.39 14.02,13.39 14.1,13.31 v1(14.17,13.31) ; U22.7 23.04,8.94 22.73,9.25 22.17,9.25 22.02,9.09 v1(21.95,9.09) 21.31,9.09 R331.2
  BOTTOM w0.102: v1(21.95,9.09) 21.68,8.82 17.41,8.82 16.94,8.36 16.13,8.36 16.13,8.36 15.8,8.36 13.61,10.54 13.61,11.4 14.17,11.96 v1(14.17,13.31)
PWM0: length 9.1
  TOP w0.102: 10.72,10.37 10.72,10.36 v1(11.23,9.86)
  BOTTOM w0.102: v1(11.23,9.86) 11.43,9.86 11.79,10.21 11.79,10.54 10.57,11.76 10.57,13.94 11.66,15.04 12.42,15.04 12.7,15.32 H10.1
PWM2: length 7.9
  TOP w0.102: v1(9.65,13.28) 9.73,13.36 R18.2 ; v1(11.43,10.36) 11.07,10.72 U1.B5
  BOTTOM w0.102: v1(11.43,10.36) 11.43,10.49 10.36,11.56 10.36,12.83 9.91,13.28 v1(9.65,13.28) 9.65,13.39 11.43,15.16 H11.1
PWM4_I2CS_SCK0: length 6.6
  TOP w0.102: U1.A5 10.95,11.9 v1(10.95,12.27)
  BOTTOM w0.102: H9.1 13.97,15.55 13.25,14.83 11.79,14.83 10.85,13.89 10.85,12.37 v1(10.95,12.27)
PWM5_I2CS_SDA0: length 7.5
  TOP w0.102: v1(12.22,11.15) 12.06,11.15 U1.B3
  PWR w0.102: H8.1 15.24,15.42 14.73,14.91 13.54,14.91 13.06,14.43 13.06,14.33 13.03,14.3 v1(13.03,13.92)
  BOTTOM w0.102: v1(12.22,11.15) 12.22,11.53 12.09,11.65 12.09,12.52 13,13.44 13,13.49 13.03,13.51 v1(13.03,13.92)
PWM6: length 8.8
  TOP w0.102: v1(11.2,12.75) 11.33,12.62 11.33,12.23 U1.A4
  BOTTOM w0.102: v1(11.2,12.75) 11.07,12.88 11.07,13.82 11.89,14.63 13.92,14.63 14.05,14.5 15.72,14.5 16.51,15.29 H7.1
PWM7: length 9
  TOP w0.102: U1.B2 12.38,11.53 12.38,11.53 12.58,11.33 v1(13.26,11.33)
  BOTTOM w0.102: v1(13.26,11.33) 13.26,11.71 13.69,12.14 13.69,13.36 14.07,13.74 16.08,13.74 17.78,15.44 H6.1
RFIN2N1: length 1.8
  TOP w0.114: U23.8 18.76,9.86 18.48,9.57 18.48,8.82 18.17,8.51 U1.A51
RFIN2N1_ANT2: length 2
  TOP w0.127: U1.A46 18.27,5.99 19.89,5.99 C454.1
RFIN2P1: length 1.8
  TOP w0.114: U1.A50 18.44,8.25 18.85,8.66 18.85,9.41 19.03,9.6 U23.9
RFIN2P1_ANT2: length 1.7
  TOP w0.127: C453.1 19.87,6.36 18.61,6.36 U1.A47
RFOUT2N1: length 1.7
  TOP w0.114: U23.6 18.06,10.56 17.78,10.29 17.11,10.29 16.75,9.92 U1.A55
RFOUT2P1: length 1.7
  TOP w0.114: U1.A54 17.03,9.67 17.27,9.92 17.93,9.92 18.32,10.3 U23.7
SDIO_D2_UART2_TXD: length 10.6
  TOP w0.102: U1.B8 10.01,9.66 10.49,9.18 10.54,9.13 v1(10.54,9.12)
  BOTTOM w0.102: H16.1 5.08,15.29 5.56,14.81 6.76,14.81 8.33,13.23 8.33,12.37 9.02,11.68 9.02,10.64 v1(10.54,9.12)
SPI_CLK_SDIO_CLK_UART2_CTS: length 6.4
  TOP w0.102: v1(9.7,11.2) 9.75,11.15 9.75,10.97 10.09,10.63 U1.A8
  BOTTOM w0.102: H14.1 7.62,14.55 8.74,13.44 8.74,12.57 9.42,11.89 9.42,11.48 v1(9.7,11.2)
SPI_CS_SDIO_CMD: length 11.2
  TOP w0.102: v1(6.32,14.15) 6.88,14.15 7.21,13.82 R13.1 7.29,13.74 8.23,12.8 8.61,12.8 8.89,12.52 8.89,11.49 8.89,9.72 U1.A11
  BOTTOM w0.102: v1(6.32,14.15) 6.2,14.27 3.58,14.27 2.54,15.32 H18.1
SPI_INT_SDIO_D1_UART2_RXD: length 7.1
  TOP w0.102: U1.A9 9.45,10.57 v1(9.45,10.72)
  BOTTOM w0.102: v1(9.45,10.72) 9.22,10.95 9.22,11.79 8.53,12.47 8.53,13.34 6.35,15.52 H15.1
SPI_MISO_SDIO_D0_UART2_RTS: length 8.8
  TOP w0.102: v1(8.59,14.15) 8.41,13.97 R11.1 ; v1(10.72,9.66) U1.B7
  BOTTOM w0.102: v1(10.72,9.66) 10.72,10.87 10.16,11.43 10.16,12.04 9.91,12.29 9.32,12.29 8.94,12.67 8.94,13.56 8.59,13.92 v1(8.59,14.15) 8.59,14.94 8.89,15.24 H13.1
SPI_MOSI_SDIO_D3: length 11.5
  TOP w0.102: v1(10.02,8.97) 10.02,8.95 9.67,9.31 U1.B9
  BOTTOM w0.102: H17.1 3.81,15.16 4.47,14.5 6.76,14.5 8.1,13.16 8.1,12.27 8.81,11.56 8.81,10.54 8.99,10.37 10.02,9.34 v1(10.02,8.97)
SPIM_CLK: length 11.1
  TOP w0.089: U1.B23 10.75,2.94
  TOP w0.102: 10.75,2.94 10.71,2.94 10.26,2.49 10.26,2.26 ; 10.09,1.86 10.26,2.03 10.26,2.26 ; 10.26,2.26 v1(10.24,2.26)
  PWR w0.102: v1(2.77,2.54) 3.02,2.29 5.66,2.29 6.76,1.19 9.6,1.19 10.24,1.83 v1(10.24,2.26)
SPIM_CS: length 16.6
  TOP w0.102: U1.A27 10.81,3.34 v1(9.45,1.98) 9.37,1.98 R308.1
  TOP w0.127: U3.1 5.28,7.49 4.6,6.81 v1(4.6,6.55)
  BOTTOM w0.102: 4.42,1.57 4.78,1.22 7.06,1.22 7.14,1.3 8.18,1.3 8.86,1.98 v1(9.45,1.98) ; 4.42,1.57 3.81,0.97 H30.1 ; 4.42,1.57 4.42,6.38 v1(4.6,6.55)
SPIM_DIO2: length 13.9
  TOP w0.102: U1.A25 9.65,3.61 9.4,3.61 8.69,2.9 8.41,2.9 v1(8.26,2.74) 7.7,2.74 R305.1 ; v1(2.74,7.32) U3.3
  PWR w0.102: v1(8.26,2.74) 7.7,2.18 6.38,2.18 5.84,2.72 3.61,2.72 2.93,3.39 2.93,6.82 2.74,7.01 v1(2.74,7.32)
SPIM_DIO3: length 8
  TOP w0.089: 9.69,4 U1.B20
  TOP w0.102: 9.69,4 9.53,3.84 9.32,3.84 8.61,3.12 7.8,3.12 R307.1 7.65,3.45 7.47,3.63 4.5,3.63 4.01,3.15 U3.7
SPIM_MISO_DIO1: length 10.1
  TOP w0.089: v1(10.9,4.7) 10.9,4.5 10.72,4.32 U1.B21
  TOP w0.102: U3.2 4.01,7.32 v1(4.06,7.26)
  BOTTOM w0.102: v1(4.06,7.26) 4.8,7.26 5.28,6.78 5.28,5.26 5.77,4.78 10.44,4.78 10.52,4.7 v1(10.9,4.7)
SPIM_MOSI_DIO0: length 11.8
  TOP w0.102: 11.07,3.97 9.44,2.34 9.19,2.34 8.51,1.65 v1(7.85,1.65) 7.65,1.85 R7.1
  PWR w0.102: v1(7.85,1.65) 7.52,1.98 6.27,1.98 5.77,2.49 3.43,2.49 2.97,2.95 1.93,2.95 v1(1.52,2.54)
USB_DNEG: length 9.3
  TOP w0.127: 8.33,5.82 8.19,5.82 7.94,5.58 7.58,5.58 6.82,4.81 2.67,4.81 2.38,4.52 1.89,4.03 0.75,4.03 0.28,3.55 H27.1
USB_DPOS: length 9
  TOP w0.127: H26.1 0.28,4.82 0.79,4.32 1.77,4.32 2.55,5.11 6.7,5.11 7.46,5.87 7.8,5.87 7.98,6.05 U1.A19
WIFI_HSUART_CTS: length 9.4
  TOP w0.102: v1(13.97,11.15) 14.01,11.15 U1.B50
  BOTTOM w0.102: H4.1 20.32,15.32 18.75,13.74 16.69,13.74 16.28,13.34 15.88,13.34 14.24,11.7 14.24,11.42 v1(13.97,11.15)
WIFI_HSUART_RTS: length 7.5
  TOP w0.102: v1(14.73,12.7) 14.76,12.67 14.76,12.25 14.55,12.05 U1.A61 ; R17.2 17.42,13.82 v1(17.14,14.1)
  BOTTOM w0.102: H5.1 19.05,15.27 17.88,14.1 v1(17.14,14.1) 16.74,14.1 16.18,13.54 15.57,13.54 v1(14.73,12.7)
WIFI_HSUART_RXD: length 9.1
  TOP w0.102: v1(15.21,12.17) 15.21,12.01 14.91,11.71 U1.A60
  BOTTOM w0.102: v1(15.21,12.17) 15.48,12.44 15.48,12.64 15.98,13.13 16.38,13.13 16.79,13.54 19.86,13.54 21.59,15.27 H3.1
WIFI_HSUART_TXD: length 11.5
  TOP w0.102: v1(14.71,10.46) 14.74,10.46 U1.B48
  BOTTOM w0.102: v1(14.71,10.46) 15.85,11.61 15.85,11.91 16.16,12.22 19.86,12.22 22.38,14.74 22.38,15.07 22.86,15.55 H2.1
WIFI_I2S_BLK1: length 2.9
  TOP w0.102: U1.A33 13.37,1.58 12.4,0.61 11.66,0.61 11.43,0.38 H36.1
WIFI_I2S_MCLK1: length 6.6
  TOP w0.102: U1.A28 10.87,2.71 10.87,2.57 v1(10.77,2.46)
  BOTTOM w0.102: v1(10.77,2.46) 10.77,2.24 10.39,1.85 10.08,1.85 9.75,1.52 8.71,1.52 8.28,1.09 7.24,1.09 7.11,0.97 6.71,0.97 6.35,0.61 H32.1
WIFI_I2S_SDI1: length 5.5
  TOP w0.102: 12.13,2.91 12.13,2.91 12.51,3.29 12.46,3.29 v1(12.4,3.23)
  BOTTOM w0.102: v1(12.4,3.23) 12.04,2.87 12.04,1.98 11.61,1.55 10.87,1.55 10.72,1.4 10.41,1.4 10.16,1.14 H35.1
WIFI_I2S_SDO1: length 4
  TOP w0.102: U1.A29 11.51,2.62 11,2.11 10.82,2.11 9.4,0.69 9.14,0.69 8.89,0.43 H34.1
WIFI_I2S_WS1: length 7.8
  TOP w0.102: v1(12.37,3.84) 12.34,3.84 11.78,3.27 U1.B24
  BOTTOM w0.102: H33.1 7.62,0.64 7.87,0.89 8.39,0.89 8.8,1.3 9.86,1.3 10.19,1.63 10.57,1.63 11.18,2.24 11.18,2.64 v1(12.37,3.84)
N34434236: length 7.1
  TOP w0.127: U1.A43 17.27,4.87 17.27,4.78 18.39,3.66 22.15,3.66 22.97,4.48 Y1.3
N34434434: length 4.5
  TOP w0.102: v1(8.46,11.35) 8.46,11.43 8.59,11.56 C19.2 ; v1(9.78,8.48) 9.78,8.48 9.31,8.95 U1.B10
  BOTTOM w0.102: v1(9.78,8.48) 9.78,8.48 9.65,8.61 9.65,9.42 8.91,10.16 8.59,10.48 8.59,11.23 v1(8.46,11.35)
N34434436: length 4.5
  TOP w0.203: 6.58,9.91 7.69,8.79 7.69,8.79 7.97,8.51 U1.A14
  TOP w0.254: L4.2 6.02,11.18 6.58,10.62 6.58,9.91
N34450965: length 4.9
  TOP w0.127: U1.A42 16.92,4.52 17.15,4.52 18.24,3.43 19.84,3.43 20.58,2.68 Y1.1
N34454485: length 1.2
  TOP w0.127: C336.1 C58.1 C59.2
N34454501: length 2.8
  TOP w0.127: C59.1 25.1,12.85 25.93,13.69 26.34,13.69
N34484478: length 1.5
  TOP w0.127: J1.1 23.04,12.55 23.47,12.12 C337.1
N34484530: length 1.2
  TOP w0.127: C336.2 C339.1 C338.1
N34527590: length 2
  TOP w0.127: U23.2 19.98,11.17 arc(20.04,11.21) 20.12,11.23 21.16,11.23 L427.1 C338.2
N344546310: length 0.6
  TOP w0.127: L427.2 C452.1

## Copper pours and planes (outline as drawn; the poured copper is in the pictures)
GND on TOP (solid shape): 4.85,0.91 0.91,0.91 0.91,1.52 4.85,1.52
GND on TOP (solid shape): 25.86,1.04 25.25,1.04 25.25,10.64 25.86,10.64
GND on TOP (solid shape): 1.52,9.17 0.91,9.17 0.91,13.28 1.52,13.28
GND on TOP (solid shape): 20.6,14.48 1.63,14.48 1.63,15.09 20.6,15.09
GND on TOP (solid shape): 25.86,0.91 15.93,0.91 15.93,1.52 25.86,1.52
GND on TOP (solid shape): 29.63,13.39 26.51,13.39 26.06,13.54 26.06,13.84 26.51,14 29.02,14 29.02,14.68 26.18,14.68 26.18,15.14 29.63,15.14
GND on TOP: 0.74,0.74 0.74,15.27 21.67,15.27 21.67,11.73 23.55,11.73 23.55,15.7 26.21,15.7 26.21,14.48 25.86,14.48 25.86,0.74 ; 7 cut-outs
GND on BOTTOM: 0.74,0.74 0.74,15.27 26.21,15.27 26.21,14.48 25.86,14.48 25.86,0.74 ; 4 cut-outs
GND on GND: 0.74,0.74 0.74,15.27 21.67,15.27 21.67,11.73 23.55,11.73 23.55,15.27 26.21,15.27 26.21,14.48 25.86,14.48 25.86,0.74
GND on PWR: 0.74,0.74 0.74,15.27 26.21,15.27 26.21,14.48 25.86,14.48 25.86,0.74
VDD33 on TOP (solid shape): 2.97,10.08 3.48,10.08 3.51,10.06 3.51,9.42 3.45,9.37 1.85,9.37 1.8,9.42 1.8,10.26 2.79,10.26
VDD33 on BOTTOM (solid shape): 2.21,10.21 2.21,9.5 2.08,9.37 0.97,9.37 0.74,9.14 0.74,8.33 0.69,8.28 0.03,8.28 -0.03,8.33 -0.03,10.11 0.13,10.26 2.16,10.26

Small or netless copper shapes (teardrops, artwork), in the pictures only: 1 on PWR

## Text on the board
DIMENSION: 100 ohm diff : | 90 ohm diff: | 14) COPPER THICKNESSES SHOWN ARE BEFORE PLATING. | 15) FABRICATE PER IPC-6012 CLASS 2 ( LATEST REVISION ) UNLESS OTHERWISE SPECIFIED. | 16) MATERIAL: FR4 , Tg 170 | 11) BOW AND TWIST: .75% MAX ALLOWABLE . | 13) PROVIDE CROSS SECTION WITH COMPLETED BOARDS. | 10) TRACE WIDTHS MUST TO BE FINISHED SIZES +/- 1 MIL ON TOP LAYER. | 12) FR4  DIELECTRIC CONSTANT 3.9~4.1@ 1GHz. | 50 ohm : | 9) TRACE WIDTHS IN ARTWORK ARE FINISHED SIZES.  DO NOT DEVIATE | 5) SEE DRILL CHART FOR FINISHED HOLE SIZES. | 6) HOLE TOLERANCE IS +/- 3 MILS UNLESS OTHERWISE SPECIFIED. | 7) SEE FILM FOR LAYER SEQUENCE. | 8) THIS IS A 4 LAYERs BOARD. | 4) SILKSCREEN:  TOP and BOTTOM SIDE, COLOR: WHITE | 1) FINISHED BOARD THICKNESS TO BE 39.37MIL +/- 10%. | 3) PLATING:  IMMERSION GOLD OVER ELECTROLESS NICKEL. | 2) SOLDERMASK TO BE LPI, COLOR :  GREEN, BOTH SIDES.. | NOTES: (UNLESS OTHERWISE SPECIFIED) | WITHOUT PRIOR AUTHORIZATION FROM ATHEROS. | (1)     L1:  5-6.5-6.5 | (1)     L1:  4.5-10-10 | (1)     L1:  5-12 | TOP SIDE LAYER 1 (0.33 oz. Cu FOIL) | GND SIDE LAYER 2 (0.5 oz. Cu FOIL) | PWR SIDE LAYER 3 (0.5 oz. Cu FOIL) | 3.2627MILS | BOTTOM SIDE LAYER 4 (0.33 oz. Cu FOIL) | CORE-  27.952MILS | 17) PLUGGED ALL VIAS BY SOLDERMASK ON BOTH SIDES
BODY_CENTER: FIGURE | SIZE | 8.0 | 16.0 | 19.69 | 43.31 | DRILL CHART: TOP to BOTTOM | ALL UNITS ARE IN MILS | PLATED | NON-PLATED | QTY | 274 | 1 | 46 | 2
